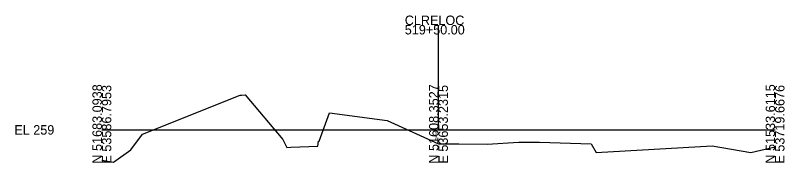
# Model space of a CAD drawing. Extents: x 6376 to 6605, y 90969 to 95005.
# Drawn here: x 6376.3 to 6604.8, y 92468.8 to 92512.5 of the extents above; entities that cross this region are included whole.
import ezdxf

# ---------------------------------------------------------------- set-up
doc = ezdxf.new("R2010")
doc.units = 0
for name, color, linetype in [('Level 10', 7, 'Continuous'), ('Level 60', 7, 'Continuous'), ('Level 63', 7, 'Continuous')]:
    doc.layers.add(name, color=color, linetype=linetype)

msp = doc.modelspace()

# ---------------------------------------------------------------- linework, layer by layer
at = {"layer": 'Level 60'}
for p, q in [((6414.05, 92477.24), (6443.04, 92488.81)), ((6443.04, 92488.81), (6443.5, 92488.86)), ((6443.5, 92488.86), (6444.59, 92488.89)), ((6444.59, 92488.89), (6455.74, 92475.72)), ((6466.51, 92475.21), (6469.61, 92483.61)), ((6469.61, 92483.61), (6486.76, 92481.33)), ((6486.76, 92481.33), (6502, 92474.44)), ((6410.64, 92472.58), (6414.05, 92477.24)), ((6455.74, 92475.72), (6457, 92473.29)), ((6466.13, 92473.66), (6466.36, 92475.2)), ((6466.36, 92475.2), (6466.51, 92475.21)), ((6502, 92474.44), (6508.03, 92474.44)), ((6508.03, 92474.44), (6516.5, 92474.32)), ((6516.5, 92474.32), (6525.84, 92474.84)), ((6525.84, 92474.84), (6532, 92474.85)), ((6532, 92474.85), (6547.38, 92474.35)), ((6547.38, 92474.35), (6548.85, 92471.84)), ((6405.49, 92468.99), (6410.64, 92472.58)), ((6457, 92473.29), (6458.09, 92473.36)), ((6458.09, 92473.36), (6466.13, 92473.66)), ((6548.85, 92471.84), (6583.29, 92473.8)), ((6583.29, 92473.8), (6594.83, 92471.87)), ((6594.83, 92471.87), (6602, 92473.49)), ((6402, 92469.55), (6405.49, 92468.99))]:
    msp.add_line(p, q, dxfattribs=at)
at = {"layer": 'Level 63'}
for p, q in [((6502, 92478.53), (6502, 92509.62)), ((6402, 92478.53), (6502, 92478.53)), ((6502, 92478.53), (6602, 92478.53))]:
    msp.add_line(p, q, dxfattribs=at)

# ---------------------------------------------------------------- texts
at = {"layer": 'Level 10'}
msp.add_text('254.91', height=0.6, rotation=90, dxfattribs=at).set_placement((6501.6, 92475.44))
at = {"layer": 'Level 63'}
for s, p in [('CLRELOC', (6492, 92509.62)), ('519+50.00', (6492, 92506.82)), ('EL 259', (6376, 92477.13))]:
    msp.add_text(s, height=2.8, dxfattribs=at).set_placement(p)
for s, p in [('N 51683.0938', (6402, 92468.53)), ('E 53586.7953', (6404.8, 92468.53)), ('N 51608.3527', (6502, 92468.53)), ('E 53653.2315', (6504.8, 92468.53)), ('N 51533.6115', (6602, 92468.53)), ('E 53719.6676', (6604.8, 92468.53))]:
    msp.add_text(s, height=2.8, rotation=90, dxfattribs=at).set_placement(p)

doc.saveas('drawing.dxf')
